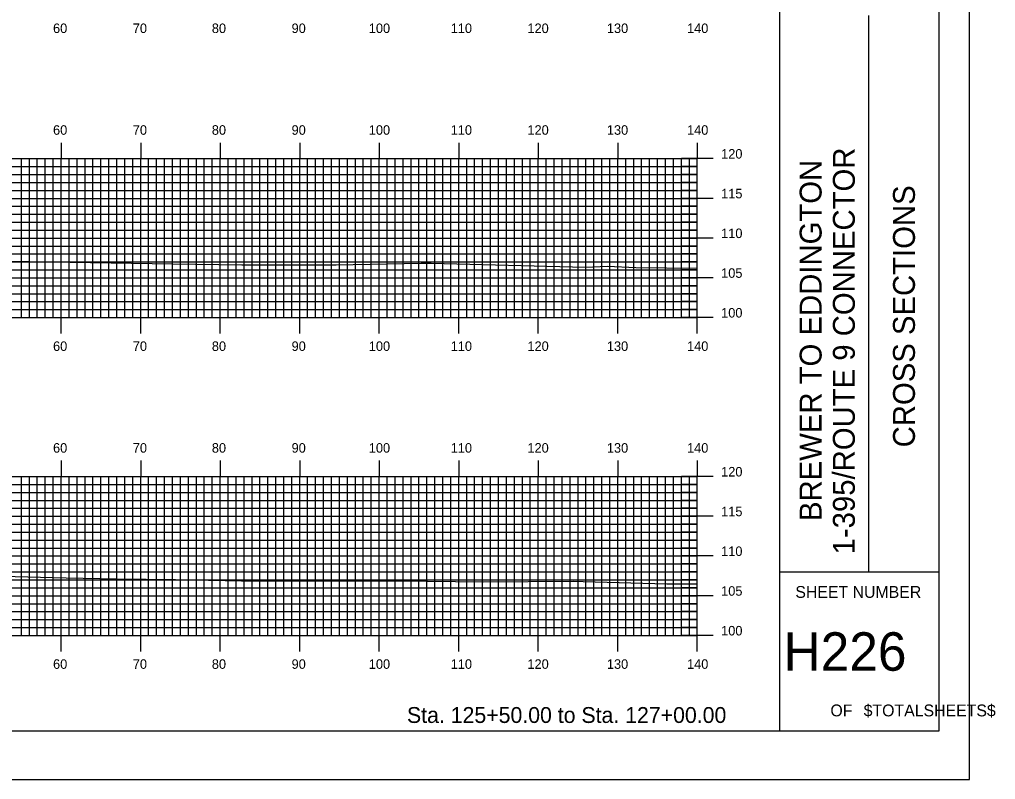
# Model space of a CAD drawing. Extents: x 1773203 to 1773546, y 442591 to 442811.
# Drawn here: x 1773423.4 to 1773546.1, y 442590.5 to 442686.2 of the extents above; entities that cross this region are included whole.
import ezdxf

# ---------------------------------------------------------------- set-up
doc = ezdxf.new("R2010")
doc.units = 0
for name, color, linetype in [('BORDER', 7, 'Continuous'), ('H_V ANNOTATION', 7, 'Continuous'), ('MAJOR', 7, 'Continuous'), ('MINOR', 7, 'Continuous'), ('PLOT BOUNDARY', 7, 'Continuous'), ('S_Roadway_Centerline', 7, 'Continuous')]:
    doc.layers.add(name, color=color, linetype=linetype)

msp = doc.modelspace()

# ---------------------------------------------------------------- linework, layer by layer
at = {"layer": 'BORDER'}
for p, q in [((1773519.03, 442596.67), (1773519.03, 442806.67)), ((1773530.21, 442616.67), (1773530.21, 442686.67)), ((1773519.03, 442616.67), (1773539.03, 442616.67))]:
    msp.add_line(p, q, dxfattribs=at)
msp.add_lwpolyline([(1773219.03, 442596.67), (1773539.03, 442596.67), (1773539.03, 442806.67), (1773219.03, 442806.67)], close=True, dxfattribs=at)
at = {"layer": 'MAJOR'}
for p, q in [((1773428.63, 442670.67), (1773428.63, 442668.67)), ((1773438.63, 442670.67), (1773438.63, 442668.67)), ((1773448.63, 442670.67), (1773448.63, 442668.67)), ((1773458.63, 442670.67), (1773458.63, 442668.67)), ((1773468.63, 442670.67), (1773468.63, 442668.67)), ((1773478.63, 442670.67), (1773478.63, 442668.67)), ((1773488.63, 442670.67), (1773488.63, 442668.67)), ((1773498.63, 442670.67), (1773498.63, 442668.67)), ((1773508.63, 442670.67), (1773508.63, 442668.67)), ((1773228.63, 442668.67), (1773508.63, 442668.67)), ((1773228.63, 442668.67), (1773508.63, 442668.67)), ((1773428.63, 442648.67), (1773428.63, 442668.67)), ((1773438.63, 442648.67), (1773438.63, 442668.67)), ((1773448.63, 442648.67), (1773448.63, 442668.67)), ((1773458.63, 442648.67), (1773458.63, 442668.67)), ((1773468.63, 442648.67), (1773468.63, 442668.67)), ((1773478.63, 442648.67), (1773478.63, 442668.67)), ((1773488.63, 442648.67), (1773488.63, 442668.67)), ((1773498.63, 442648.67), (1773498.63, 442668.67)), ((1773510.64, 442668.67), (1773506.63, 442668.67)), ((1773508.63, 442648.67), (1773508.63, 442668.67)), ((1773508.63, 442648.67), (1773508.63, 442668.67)), ((1773228.63, 442663.67), (1773508.63, 442663.67)), ((1773510.64, 442663.67), (1773506.63, 442663.67)), ((1773228.63, 442658.67), (1773508.63, 442658.67)), ((1773510.64, 442658.67), (1773506.63, 442658.67)), ((1773228.63, 442653.67), (1773508.63, 442653.67)), ((1773510.64, 442653.67), (1773506.63, 442653.67)), ((1773228.63, 442648.67), (1773508.63, 442648.67)), ((1773228.63, 442648.67), (1773508.63, 442648.67)), ((1773428.63, 442646.66), (1773428.63, 442648.67)), ((1773438.63, 442646.66), (1773438.63, 442648.67)), ((1773448.63, 442646.66), (1773448.63, 442648.67)), ((1773458.63, 442646.66), (1773458.63, 442648.67)), ((1773468.63, 442646.66), (1773468.63, 442648.67)), ((1773478.63, 442646.66), (1773478.63, 442648.67)), ((1773488.63, 442646.66), (1773488.63, 442648.67)), ((1773498.63, 442646.66), (1773498.63, 442648.67)), ((1773510.64, 442648.67), (1773506.63, 442648.67)), ((1773508.63, 442646.66), (1773508.63, 442648.67)), ((1773428.63, 442630.67), (1773428.63, 442628.67)), ((1773438.63, 442630.67), (1773438.63, 442628.67)), ((1773448.63, 442630.67), (1773448.63, 442628.67)), ((1773458.63, 442630.67), (1773458.63, 442628.67)), ((1773468.63, 442630.67), (1773468.63, 442628.67)), ((1773478.63, 442630.67), (1773478.63, 442628.67)), ((1773488.63, 442630.67), (1773488.63, 442628.67)), ((1773498.63, 442630.67), (1773498.63, 442628.67)), ((1773508.63, 442630.67), (1773508.63, 442628.67)), ((1773228.63, 442628.67), (1773508.63, 442628.67)), ((1773228.63, 442628.67), (1773508.63, 442628.67)), ((1773428.63, 442608.67), (1773428.63, 442628.67)), ((1773438.63, 442608.67), (1773438.63, 442628.67)), ((1773448.63, 442608.67), (1773448.63, 442628.67)), ((1773458.63, 442608.67), (1773458.63, 442628.67)), ((1773468.63, 442608.67), (1773468.63, 442628.67)), ((1773478.63, 442608.67), (1773478.63, 442628.67)), ((1773488.63, 442608.67), (1773488.63, 442628.67)), ((1773498.63, 442608.67), (1773498.63, 442628.67)), ((1773510.64, 442628.67), (1773506.63, 442628.67)), ((1773508.63, 442608.67), (1773508.63, 442628.67)), ((1773508.63, 442608.67), (1773508.63, 442628.67)), ((1773228.63, 442623.67), (1773508.63, 442623.67)), ((1773510.64, 442623.67), (1773506.63, 442623.67)), ((1773228.63, 442618.67), (1773508.63, 442618.67)), ((1773510.64, 442618.67), (1773506.63, 442618.67)), ((1773228.63, 442613.67), (1773508.63, 442613.67)), ((1773510.64, 442613.67), (1773506.63, 442613.67)), ((1773228.63, 442608.67), (1773508.63, 442608.67)), ((1773228.63, 442608.67), (1773508.63, 442608.67)), ((1773428.63, 442606.66), (1773428.63, 442608.67)), ((1773438.63, 442606.66), (1773438.63, 442608.67)), ((1773448.63, 442606.66), (1773448.63, 442608.67)), ((1773458.63, 442606.66), (1773458.63, 442608.67)), ((1773468.63, 442606.66), (1773468.63, 442608.67)), ((1773478.63, 442606.66), (1773478.63, 442608.67)), ((1773488.63, 442606.66), (1773488.63, 442608.67)), ((1773498.63, 442606.66), (1773498.63, 442608.67)), ((1773510.64, 442608.67), (1773506.63, 442608.67)), ((1773508.63, 442606.66), (1773508.63, 442608.67))]:
    msp.add_line(p, q, dxfattribs=at)
at = {"layer": 'MINOR'}
for p, q in [((1773423.63, 442648.67), (1773423.63, 442668.67)), ((1773424.63, 442648.67), (1773424.63, 442668.67)), ((1773425.63, 442648.67), (1773425.63, 442668.67)), ((1773426.63, 442648.67), (1773426.63, 442668.67)), ((1773427.63, 442648.67), (1773427.63, 442668.67)), ((1773429.63, 442648.67), (1773429.63, 442668.67)), ((1773430.63, 442648.67), (1773430.63, 442668.67)), ((1773431.63, 442648.67), (1773431.63, 442668.67)), ((1773432.63, 442648.67), (1773432.63, 442668.67)), ((1773433.63, 442648.67), (1773433.63, 442668.67)), ((1773434.63, 442648.67), (1773434.63, 442668.67)), ((1773435.63, 442648.67), (1773435.63, 442668.67)), ((1773436.63, 442648.67), (1773436.63, 442668.67)), ((1773437.63, 442648.67), (1773437.63, 442668.67)), ((1773439.63, 442648.67), (1773439.63, 442668.67)), ((1773440.63, 442648.67), (1773440.63, 442668.67)), ((1773441.63, 442648.67), (1773441.63, 442668.67)), ((1773442.63, 442648.67), (1773442.63, 442668.67)), ((1773443.63, 442648.67), (1773443.63, 442668.67)), ((1773444.63, 442648.67), (1773444.63, 442668.67)), ((1773445.63, 442648.67), (1773445.63, 442668.67)), ((1773446.63, 442648.67), (1773446.63, 442668.67)), ((1773447.63, 442648.67), (1773447.63, 442668.67)), ((1773449.63, 442648.67), (1773449.63, 442668.67)), ((1773450.63, 442648.67), (1773450.63, 442668.67)), ((1773451.63, 442648.67), (1773451.63, 442668.67)), ((1773452.63, 442648.67), (1773452.63, 442668.67)), ((1773453.63, 442648.67), (1773453.63, 442668.67)), ((1773454.63, 442648.67), (1773454.63, 442668.67)), ((1773455.63, 442648.67), (1773455.63, 442668.67)), ((1773456.63, 442648.67), (1773456.63, 442668.67)), ((1773457.63, 442648.67), (1773457.63, 442668.67)), ((1773459.63, 442648.67), (1773459.63, 442668.67)), ((1773460.63, 442648.67), (1773460.63, 442668.67)), ((1773461.63, 442648.67), (1773461.63, 442668.67)), ((1773462.63, 442648.67), (1773462.63, 442668.67)), ((1773463.63, 442648.67), (1773463.63, 442668.67)), ((1773464.63, 442648.67), (1773464.63, 442668.67)), ((1773465.63, 442648.67), (1773465.63, 442668.67)), ((1773466.63, 442648.67), (1773466.63, 442668.67)), ((1773467.63, 442648.67), (1773467.63, 442668.67)), ((1773469.63, 442648.67), (1773469.63, 442668.67)), ((1773470.63, 442648.67), (1773470.63, 442668.67)), ((1773471.63, 442648.67), (1773471.63, 442668.67)), ((1773472.63, 442648.67), (1773472.63, 442668.67)), ((1773473.63, 442648.67), (1773473.63, 442668.67)), ((1773474.63, 442648.67), (1773474.63, 442668.67)), ((1773475.63, 442648.67), (1773475.63, 442668.67)), ((1773476.63, 442648.67), (1773476.63, 442668.67)), ((1773477.63, 442648.67), (1773477.63, 442668.67)), ((1773479.63, 442648.67), (1773479.63, 442668.67)), ((1773480.63, 442648.67), (1773480.63, 442668.67)), ((1773481.63, 442648.67), (1773481.63, 442668.67)), ((1773482.63, 442648.67), (1773482.63, 442668.67)), ((1773483.63, 442648.67), (1773483.63, 442668.67)), ((1773484.63, 442648.67), (1773484.63, 442668.67)), ((1773485.63, 442648.67), (1773485.63, 442668.67)), ((1773486.63, 442648.67), (1773486.63, 442668.67)), ((1773487.63, 442648.67), (1773487.63, 442668.67)), ((1773489.63, 442648.67), (1773489.63, 442668.67)), ((1773490.63, 442648.67), (1773490.63, 442668.67)), ((1773491.63, 442648.67), (1773491.63, 442668.67)), ((1773492.63, 442648.67), (1773492.63, 442668.67)), ((1773493.63, 442648.67), (1773493.63, 442668.67)), ((1773494.63, 442648.67), (1773494.63, 442668.67)), ((1773495.63, 442648.67), (1773495.63, 442668.67)), ((1773496.63, 442648.67), (1773496.63, 442668.67)), ((1773497.63, 442648.67), (1773497.63, 442668.67)), ((1773499.63, 442648.67), (1773499.63, 442668.67)), ((1773500.63, 442648.67), (1773500.63, 442668.67)), ((1773501.63, 442648.67), (1773501.63, 442668.67)), ((1773502.63, 442648.67), (1773502.63, 442668.67)), ((1773503.63, 442648.67), (1773503.63, 442668.67)), ((1773504.63, 442648.67), (1773504.63, 442668.67)), ((1773505.63, 442648.67), (1773505.63, 442668.67)), ((1773506.63, 442648.67), (1773506.63, 442668.67)), ((1773507.63, 442648.67), (1773507.63, 442668.67)), ((1773228.63, 442667.67), (1773508.63, 442667.67)), ((1773508.63, 442667.67), (1773506.63, 442667.67)), ((1773228.63, 442666.67), (1773508.63, 442666.67)), ((1773508.63, 442666.67), (1773506.63, 442666.67)), ((1773228.63, 442665.67), (1773508.63, 442665.67)), ((1773228.63, 442664.67), (1773508.63, 442664.67)), ((1773508.63, 442665.67), (1773506.63, 442665.67)), ((1773508.63, 442664.67), (1773506.63, 442664.67)), ((1773228.63, 442662.67), (1773508.63, 442662.67)), ((1773508.63, 442662.67), (1773506.63, 442662.67)), ((1773228.63, 442661.67), (1773508.63, 442661.67)), ((1773508.63, 442661.67), (1773506.63, 442661.67)), ((1773228.63, 442660.67), (1773508.63, 442660.67)), ((1773228.63, 442659.67), (1773508.63, 442659.67)), ((1773508.63, 442660.67), (1773506.63, 442660.67)), ((1773508.63, 442659.67), (1773506.63, 442659.67)), ((1773228.63, 442657.67), (1773508.63, 442657.67)), ((1773508.63, 442657.67), (1773506.63, 442657.67)), ((1773228.63, 442656.67), (1773508.63, 442656.67)), ((1773508.63, 442656.67), (1773506.63, 442656.67)), ((1773228.63, 442655.67), (1773508.63, 442655.67)), ((1773508.63, 442655.67), (1773506.63, 442655.67)), ((1773228.63, 442654.67), (1773508.63, 442654.67)), ((1773508.63, 442654.67), (1773506.63, 442654.67)), ((1773228.63, 442652.67), (1773508.63, 442652.67)), ((1773508.63, 442652.67), (1773506.63, 442652.67)), ((1773228.63, 442651.67), (1773508.63, 442651.67)), ((1773508.63, 442651.67), (1773506.63, 442651.67)), ((1773228.63, 442650.67), (1773508.63, 442650.67)), ((1773508.63, 442650.67), (1773506.63, 442650.67)), ((1773228.63, 442649.67), (1773508.63, 442649.67)), ((1773508.63, 442649.67), (1773506.63, 442649.67)), ((1773423.63, 442608.67), (1773423.63, 442628.67)), ((1773424.63, 442608.67), (1773424.63, 442628.67)), ((1773425.63, 442608.67), (1773425.63, 442628.67)), ((1773426.63, 442608.67), (1773426.63, 442628.67)), ((1773427.63, 442608.67), (1773427.63, 442628.67)), ((1773429.63, 442608.67), (1773429.63, 442628.67)), ((1773430.63, 442608.67), (1773430.63, 442628.67)), ((1773431.63, 442608.67), (1773431.63, 442628.67)), ((1773432.63, 442608.67), (1773432.63, 442628.67)), ((1773433.63, 442608.67), (1773433.63, 442628.67)), ((1773434.63, 442608.67), (1773434.63, 442628.67)), ((1773435.63, 442608.67), (1773435.63, 442628.67)), ((1773436.63, 442608.67), (1773436.63, 442628.67)), ((1773437.63, 442608.67), (1773437.63, 442628.67)), ((1773439.63, 442608.67), (1773439.63, 442628.67)), ((1773440.63, 442608.67), (1773440.63, 442628.67)), ((1773441.63, 442608.67), (1773441.63, 442628.67)), ((1773442.63, 442608.67), (1773442.63, 442628.67)), ((1773443.63, 442608.67), (1773443.63, 442628.67)), ((1773444.63, 442608.67), (1773444.63, 442628.67)), ((1773445.63, 442608.67), (1773445.63, 442628.67)), ((1773446.63, 442608.67), (1773446.63, 442628.67)), ((1773447.63, 442608.67), (1773447.63, 442628.67)), ((1773449.63, 442608.67), (1773449.63, 442628.67)), ((1773450.63, 442608.67), (1773450.63, 442628.67)), ((1773451.63, 442608.67), (1773451.63, 442628.67)), ((1773452.63, 442608.67), (1773452.63, 442628.67)), ((1773453.63, 442608.67), (1773453.63, 442628.67)), ((1773454.63, 442608.67), (1773454.63, 442628.67)), ((1773455.63, 442608.67), (1773455.63, 442628.67)), ((1773456.63, 442608.67), (1773456.63, 442628.67)), ((1773457.63, 442608.67), (1773457.63, 442628.67)), ((1773459.63, 442608.67), (1773459.63, 442628.67)), ((1773460.63, 442608.67), (1773460.63, 442628.67)), ((1773461.63, 442608.67), (1773461.63, 442628.67)), ((1773462.63, 442608.67), (1773462.63, 442628.67)), ((1773463.63, 442608.67), (1773463.63, 442628.67)), ((1773464.63, 442608.67), (1773464.63, 442628.67)), ((1773465.63, 442608.67), (1773465.63, 442628.67)), ((1773466.63, 442608.67), (1773466.63, 442628.67)), ((1773467.63, 442608.67), (1773467.63, 442628.67)), ((1773469.63, 442608.67), (1773469.63, 442628.67)), ((1773470.63, 442608.67), (1773470.63, 442628.67)), ((1773471.63, 442608.67), (1773471.63, 442628.67)), ((1773472.63, 442608.67), (1773472.63, 442628.67)), ((1773473.63, 442608.67), (1773473.63, 442628.67)), ((1773474.63, 442608.67), (1773474.63, 442628.67)), ((1773475.63, 442608.67), (1773475.63, 442628.67)), ((1773476.63, 442608.67), (1773476.63, 442628.67)), ((1773477.63, 442608.67), (1773477.63, 442628.67)), ((1773479.63, 442608.67), (1773479.63, 442628.67)), ((1773480.63, 442608.67), (1773480.63, 442628.67)), ((1773481.63, 442608.67), (1773481.63, 442628.67)), ((1773482.63, 442608.67), (1773482.63, 442628.67)), ((1773483.63, 442608.67), (1773483.63, 442628.67)), ((1773484.63, 442608.67), (1773484.63, 442628.67)), ((1773485.63, 442608.67), (1773485.63, 442628.67)), ((1773486.63, 442608.67), (1773486.63, 442628.67)), ((1773487.63, 442608.67), (1773487.63, 442628.67)), ((1773489.63, 442608.67), (1773489.63, 442628.67)), ((1773490.63, 442608.67), (1773490.63, 442628.67)), ((1773491.63, 442608.67), (1773491.63, 442628.67)), ((1773492.63, 442608.67), (1773492.63, 442628.67)), ((1773493.63, 442608.67), (1773493.63, 442628.67)), ((1773494.63, 442608.67), (1773494.63, 442628.67)), ((1773495.63, 442608.67), (1773495.63, 442628.67)), ((1773496.63, 442608.67), (1773496.63, 442628.67)), ((1773497.63, 442608.67), (1773497.63, 442628.67)), ((1773499.63, 442608.67), (1773499.63, 442628.67)), ((1773500.63, 442608.67), (1773500.63, 442628.67)), ((1773501.63, 442608.67), (1773501.63, 442628.67)), ((1773502.63, 442608.67), (1773502.63, 442628.67)), ((1773503.63, 442608.67), (1773503.63, 442628.67)), ((1773504.63, 442608.67), (1773504.63, 442628.67)), ((1773505.63, 442608.67), (1773505.63, 442628.67)), ((1773506.63, 442608.67), (1773506.63, 442628.67)), ((1773507.63, 442608.67), (1773507.63, 442628.67)), ((1773228.63, 442627.67), (1773508.63, 442627.67)), ((1773228.63, 442626.67), (1773508.63, 442626.67)), ((1773508.63, 442627.67), (1773506.63, 442627.67)), ((1773508.63, 442626.67), (1773506.63, 442626.67)), ((1773228.63, 442625.67), (1773508.63, 442625.67)), ((1773508.63, 442625.67), (1773506.63, 442625.67)), ((1773228.63, 442624.67), (1773508.63, 442624.67)), ((1773508.63, 442624.67), (1773506.63, 442624.67)), ((1773228.63, 442622.67), (1773508.63, 442622.67)), ((1773228.63, 442621.67), (1773508.63, 442621.67)), ((1773508.63, 442622.67), (1773506.63, 442622.67)), ((1773508.63, 442621.67), (1773506.63, 442621.67)), ((1773228.63, 442620.67), (1773508.63, 442620.67)), ((1773508.63, 442620.67), (1773506.63, 442620.67)), ((1773228.63, 442619.67), (1773508.63, 442619.67)), ((1773508.63, 442619.67), (1773506.63, 442619.67)), ((1773228.63, 442617.67), (1773508.63, 442617.67)), ((1773508.63, 442617.67), (1773506.63, 442617.67)), ((1773228.63, 442616.67), (1773508.63, 442616.67)), ((1773228.63, 442615.67), (1773508.63, 442615.67)), ((1773508.63, 442616.67), (1773506.63, 442616.67)), ((1773508.63, 442615.67), (1773506.63, 442615.67)), ((1773228.63, 442614.67), (1773508.63, 442614.67)), ((1773508.63, 442614.67), (1773506.63, 442614.67)), ((1773228.63, 442612.67), (1773508.63, 442612.67)), ((1773508.63, 442612.67), (1773506.63, 442612.67)), ((1773228.63, 442611.67), (1773508.63, 442611.67)), ((1773228.63, 442610.67), (1773508.63, 442610.67)), ((1773508.63, 442611.67), (1773506.63, 442611.67)), ((1773508.63, 442610.67), (1773506.63, 442610.67)), ((1773228.63, 442609.67), (1773508.63, 442609.67)), ((1773508.63, 442609.67), (1773506.63, 442609.67))]:
    msp.add_line(p, q, dxfattribs=at)
at = {"layer": 'PLOT BOUNDARY'}
msp.add_lwpolyline([(1773202.85, 442590.55), (1773542.85, 442590.55), (1773542.85, 442810.55), (1773202.85, 442810.55)], close=True, dxfattribs=at)
at = {"layer": 'S_Roadway_Centerline'}
for points in [[(1773415.52, 442655.83), (1773424.52, 442655.74), (1773427.53, 442655.68), (1773429.77, 442655.62), (1773442.63, 442655.43), (1773451.34, 442655.32), (1773463.22, 442655.29), (1773473.91, 442655.52), (1773475.16, 442655.5), (1773494.56, 442655), (1773497.33, 442655.12), (1773500.89, 442654.97), (1773508.63, 442654.88)], [(1773417.97, 442616.21), (1773429.28, 442615.94), (1773435.64, 442615.8), (1773443.01, 442615.72), (1773451.31, 442615.55), (1773468.42, 442615.55), (1773471.16, 442615.55), (1773481.76, 442615.41), (1773493.02, 442615.49), (1773494.27, 442615.47), (1773504.81, 442615.16), (1773508.63, 442615.18)]]:
    msp.add_lwpolyline(points, dxfattribs=at)

# ---------------------------------------------------------------- texts
at = {"layer": 'BORDER'}
for s, p in [('1-395/ROUTE 9 CONNECTOR', (1773528.44, 442618.87)), ('BREWER TO EDDINGTON', (1773524.26, 442623.07)), ('CROSS SECTIONS', (1773536, 442632.34))]:
    msp.add_text(s, height=2.7557, rotation=90, dxfattribs=at).set_placement(p)
for s, height, p in [('SHEET NUMBER', 1.4905, (1773520.96, 442613.4)), ('H226', 4.839, (1773519.47, 442604.23)), ('OF', 1.491, (1773525.37, 442598.49)), ('$TOTALSHEETS$', 1.4905, (1773529.55, 442598.49))]:
    msp.add_text(s, height=height, dxfattribs=at).set_placement(p)
at = {"layer": 'H_V ANNOTATION'}
for s, height, p in [('60', 1.2, (1773427.61, 442684.47)), ('70', 1.2, (1773437.64, 442684.47)), ('80', 1.2, (1773447.58, 442684.47)), ('90', 1.2, (1773457.61, 442684.47)), ('100', 1.2, (1773467.32, 442684.47)), ('110', 1.2, (1773477.62, 442684.47)), ('120', 1.2, (1773487.27, 442684.47)), ('130', 1.2, (1773497.26, 442684.47)), ('140', 1.2, (1773507.34, 442684.47)), ('60', 1.2, (1773427.61, 442671.67)), ('70', 1.2, (1773437.64, 442671.67)), ('80', 1.2, (1773447.58, 442671.67)), ('90', 1.2, (1773457.61, 442671.67)), ('100', 1.2, (1773467.32, 442671.67)), ('110', 1.2, (1773477.62, 442671.67)), ('120', 1.2, (1773487.27, 442671.67)), ('130', 1.2, (1773497.26, 442671.67)), ('140', 1.2, (1773507.34, 442671.67)), ('120', 1.2, (1773511.63, 442668.67)), ('115', 1.2, (1773511.63, 442663.67)), ('110', 1.2, (1773511.63, 442658.67)), ('105', 1.2, (1773511.63, 442653.67)), ('100', 1.2, (1773511.63, 442648.67)), ('60', 1.2, (1773427.61, 442644.47)), ('70', 1.2, (1773437.64, 442644.47)), ('80', 1.2, (1773447.58, 442644.47)), ('90', 1.2, (1773457.61, 442644.47)), ('100', 1.2, (1773467.32, 442644.47)), ('110', 1.2, (1773477.62, 442644.47)), ('120', 1.2, (1773487.27, 442644.47)), ('130', 1.2, (1773497.26, 442644.47)), ('140', 1.2, (1773507.34, 442644.47)), ('60', 1.2, (1773427.61, 442631.67)), ('70', 1.2, (1773437.64, 442631.67)), ('80', 1.2, (1773447.58, 442631.67)), ('90', 1.2, (1773457.61, 442631.67)), ('100', 1.2, (1773467.32, 442631.67)), ('110', 1.2, (1773477.62, 442631.67)), ('120', 1.2, (1773487.27, 442631.67)), ('130', 1.2, (1773497.26, 442631.67)), ('140', 1.2, (1773507.34, 442631.67)), ('120', 1.2, (1773511.63, 442628.67)), ('115', 1.2, (1773511.63, 442623.67)), ('110', 1.2, (1773511.63, 442618.67)), ('105', 1.2, (1773511.63, 442613.67)), ('100', 1.2, (1773511.63, 442608.67)), ('60', 1.2, (1773427.61, 442604.47)), ('70', 1.2, (1773437.64, 442604.47)), ('80', 1.2, (1773447.58, 442604.47)), ('90', 1.2, (1773457.61, 442604.47)), ('100', 1.2, (1773467.32, 442604.47)), ('110', 1.2, (1773477.62, 442604.47)), ('120', 1.2, (1773487.27, 442604.47)), ('130', 1.2, (1773497.26, 442604.47)), ('140', 1.2, (1773507.34, 442604.47)), ('Sta. 125+50.00 to Sta. 127+00.00', 2.0004, (1773472.12, 442597.66))]:
    msp.add_text(s, height=height, dxfattribs=at).set_placement(p)

doc.saveas('drawing.dxf')
